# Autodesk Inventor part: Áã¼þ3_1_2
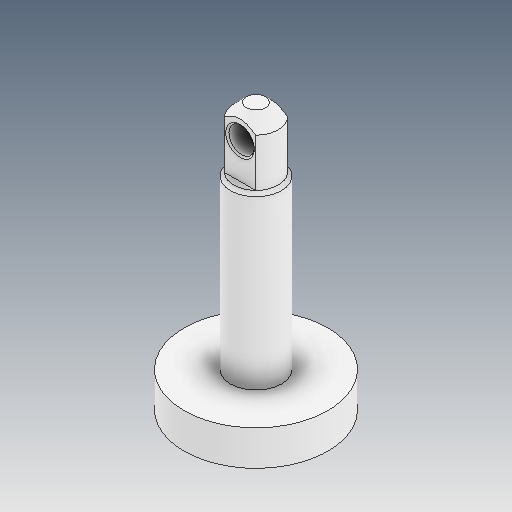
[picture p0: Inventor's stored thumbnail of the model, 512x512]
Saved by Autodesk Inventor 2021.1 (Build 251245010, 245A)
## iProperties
Created: 2021-05
Part Number: Áã¼þ3_1_2
Material: Ogólny
Document SubType Name: Modeling
Designer: user
Density: 1 g/cm^3
Appearance: Domyślna
Author: user
Revision Number: ÈÎºÎ
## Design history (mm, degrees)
feature "ÊäÈë1"
node "Bryła1"
